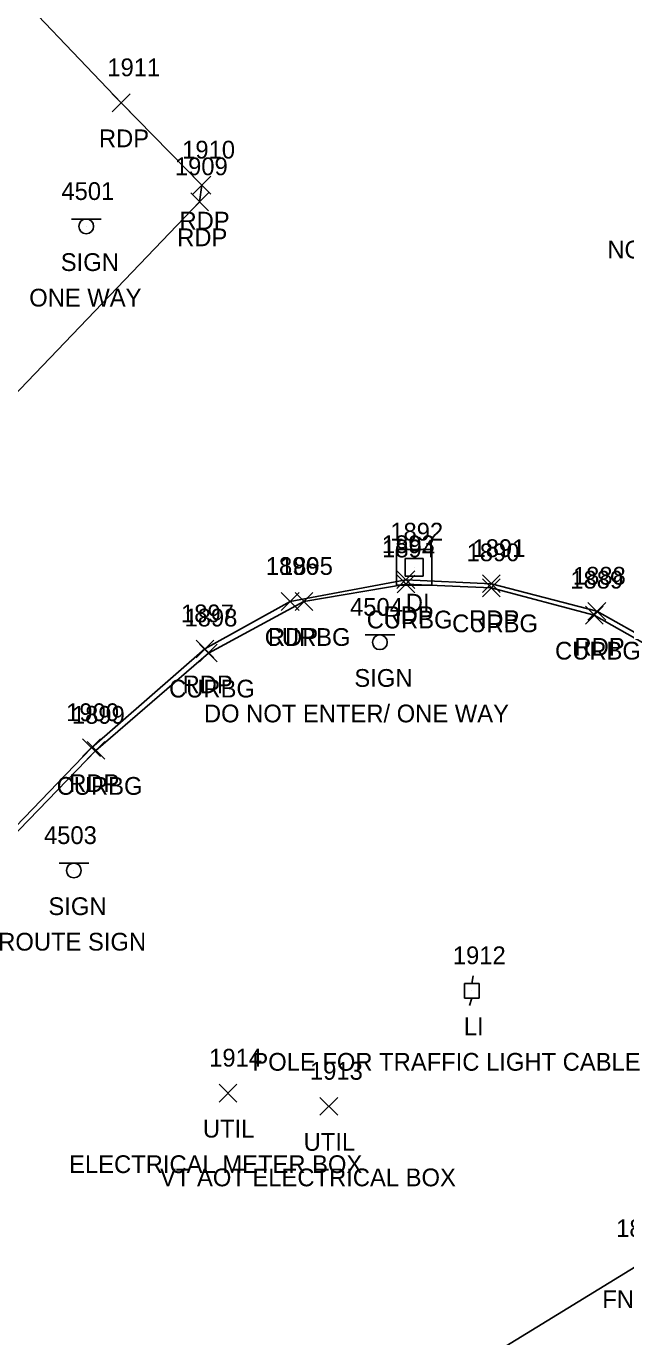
# Model space of a CAD drawing. Extents: x 1690689 to 1696275, y 438760 to 444007.
# Drawn here: x 1691729.4 to 1691796.9, y 439182.5 to 439330.1 of the extents above; entities that cross this region are included whole.
import ezdxf

# ---------------------------------------------------------------- set-up
doc = ezdxf.new("R2010")
doc.units = 0
for name, color, linetype in [('D_A', 7, 'Continuous'), ('D_I', 7, 'Continuous'), ('DS', 7, 'Continuous'), ('L_A', 7, 'Continuous'), ('L_I', 7, 'Continuous'), ('LFNC', 7, 'Continuous'), ('P_A', 7, 'Continuous'), ('P_I', 7, 'Continuous'), ('P_TIC', 7, 'Continuous'), ('PET', 7, 'Continuous'), ('R_A', 7, 'Continuous'), ('R_I', 7, 'Continuous'), ('R_TIC', 7, 'Continuous'), ('RC', 7, 'Continuous'), ('S_A', 7, 'Continuous'), ('S_C', 7, 'Continuous'), ('S_I', 7, 'Continuous'), ('SSGN', 7, 'Continuous'), ('U_A', 7, 'Continuous'), ('U_C', 7, 'Continuous'), ('U_I', 7, 'Continuous'), ('UDEFAULT', 7, 'Continuous'), ('ULP', 7, 'Continuous')]:
    doc.layers.add(name, color=color, linetype=linetype)

msp = doc.modelspace()

# ---------------------------------------------------------------- linework, layer by layer
at = {"layer": 'DS'}
for p, q in [((1691771.1, 439271.16), (1691775.1, 439271.16)), ((1691771.1, 439267.16), (1691771.1, 439271.16)), ((1691772.1, 439268.16), (1691772.1, 439270.16)), ((1691772.1, 439270.16), (1691774.1, 439270.16)), ((1691774.1, 439270.16), (1691774.1, 439268.16)), ((1691775.1, 439271.16), (1691775.1, 439267.16)), ((1691773.11, 439269.17), (1691773.11, 439269.17)), ((1691773.11, 439269.17), (1691773.11, 439269.17)), ((1691775.1, 439267.16), (1691771.1, 439267.16)), ((1691774.1, 439268.16), (1691772.1, 439268.16))]:
    msp.add_line(p, q, dxfattribs=at)
at = {"layer": 'LFNC'}
msp.add_lwpolyline([(1691757.36, 439165.44), (1691798.52, 439190.71), (1691844.54, 439219.14)], dxfattribs=at)
at = {"layer": 'P_TIC'}
for points in [[(1691739.13, 439320.47), (1691741.13, 439322.47)], [(1691741.13, 439320.47), (1691739.13, 439322.47)], [(1691748.2, 439311.2), (1691750.2, 439313.2)], [(1691750.2, 439311.2), (1691748.2, 439313.2)], [(1691747.95, 439309.32), (1691749.95, 439311.32)], [(1691749.95, 439309.32), (1691747.95, 439311.32)], [(1691771.16, 439266.75), (1691773.16, 439268.75)], [(1691773.16, 439266.75), (1691771.16, 439268.75)], [(1691780.79, 439266.31), (1691782.79, 439268.31)], [(1691782.79, 439266.31), (1691780.79, 439268.31)], [(1691758.15, 439264.3), (1691760.15, 439266.3)], [(1691760.15, 439264.3), (1691758.15, 439266.3)], [(1691792.66, 439263.2), (1691794.66, 439265.2)], [(1691794.66, 439263.2), (1691792.66, 439265.2)], [(1691748.55, 439258.96), (1691750.55, 439260.96)], [(1691750.55, 439258.96), (1691748.55, 439260.96)], [(1691735.79, 439247.83), (1691737.79, 439249.83)], [(1691737.79, 439247.83), (1691735.79, 439249.83)]]:
    msp.add_lwpolyline(points, dxfattribs=at)
at = {"layer": 'PET'}
for points in [[(1691635.64, 439190.05), (1691676.02, 439233.65), (1691723.65, 439283.92), (1691748.95, 439310.32), (1691749.2, 439312.2), (1691740.13, 439321.47), (1691725.27, 439337.07), (1691702.51, 439363.5), (1691678.2, 439394.68), (1691673.58, 439401.13), (1691654.57, 439427.19), (1691640.83, 439446.56), (1691618.23, 439480.22), (1691600.47, 439509.04), (1691582.54, 439539.92), (1691568.85, 439565.16), (1691555.7, 439590.13)], [(1691879.71, 439146.4), (1691887.29, 439151.26), (1691891.2, 439160.18), (1691892.92, 439173.27), (1691891.62, 439183.5), (1691889.41, 439189.26), (1691882.28, 439196.79), (1691847.76, 439223.08), (1691819.3, 439246.34), (1691802.22, 439259.4), (1691793.66, 439264.2), (1691781.79, 439267.31), (1691772.16, 439267.75), (1691759.15, 439265.3), (1691749.55, 439259.96), (1691736.79, 439248.83), (1691704.51, 439215.28), (1691660.95, 439169.53)]]:
    msp.add_lwpolyline(points, dxfattribs=at)
at = {"layer": 'R_TIC'}
for points in [[(1691771.18, 439266.27), (1691773.18, 439268.27)], [(1691773.18, 439266.27), (1691771.18, 439268.27)], [(1691780.78, 439265.84), (1691782.78, 439267.84)], [(1691782.78, 439265.84), (1691780.78, 439267.84)], [(1691759.7, 439264.3), (1691761.7, 439266.3)], [(1691761.7, 439264.3), (1691759.7, 439266.3)], [(1691792.37, 439262.76), (1691794.37, 439264.76)], [(1691794.37, 439262.76), (1691792.37, 439264.76)], [(1691748.94, 439258.49), (1691750.94, 439260.49)], [(1691750.94, 439258.49), (1691748.94, 439260.49)], [(1691736.29, 439247.53), (1691738.29, 439249.53)], [(1691738.29, 439247.53), (1691736.29, 439249.53)]]:
    msp.add_lwpolyline(points, dxfattribs=at)
at = {"layer": 'RC'}
msp.add_lwpolyline([(1691891.4, 439183.61), (1691888.94, 439188.91), (1691881.87, 439196.3), (1691847.41, 439222.5), (1691819.04, 439246.01), (1691801.91, 439258.9), (1691793.37, 439263.76), (1691781.78, 439266.84), (1691772.18, 439267.27), (1691760.7, 439265.3), (1691749.94, 439259.49), (1691737.29, 439248.53), (1691704.84, 439214.94), (1691660.93, 439168.79)], dxfattribs=at)
at = {"layer": 'SSGN'}
for p, q in [((1691734.55, 439308.38), (1691737.88, 439308.38)), ((1691736.19, 439307.55), (1691736.19, 439307.55)), ((1691767.59, 439261.54), (1691770.92, 439261.54)), ((1691769.24, 439260.71), (1691769.24, 439260.71)), ((1691733.16, 439235.83), (1691736.49, 439235.83)), ((1691734.8, 439235), (1691734.8, 439235))]:
    msp.add_line(p, q, dxfattribs=at)
for centre in [(1691736.19, 439307.55), (1691769.24, 439260.71), (1691734.8, 439235)]:
    msp.add_circle(centre, 0.833, dxfattribs=at)
at = {"layer": 'UDEFAULT'}
for points in [[(1691751.16, 439208.92), (1691753.16, 439210.92)], [(1691753.16, 439208.92), (1691751.16, 439210.92)], [(1691762.49, 439207.43), (1691764.49, 439209.43)], [(1691764.49, 439207.43), (1691762.49, 439209.43)]]:
    msp.add_lwpolyline(points, dxfattribs=at)
at = {"layer": 'ULP'}
for p, q in [((1691779.75, 439223.12), (1691779.58, 439222.29)), ((1691778.75, 439220.62), (1691778.75, 439222.29)), ((1691778.75, 439222.29), (1691780.41, 439222.29)), ((1691779.58, 439221.45), (1691779.58, 439221.45)), ((1691780.41, 439222.29), (1691780.41, 439220.62)), ((1691780.41, 439220.62), (1691778.75, 439220.62)), ((1691779.33, 439219.79), (1691779.58, 439220.62))]:
    msp.add_line(p, q, dxfattribs=at)

# ---------------------------------------------------------------- texts
at = {"layer": 'D_A'}
msp.add_text('DI', height=2, dxfattribs=at).set_placement((1691772.16, 439264.17))
at = {"layer": 'D_I'}
msp.add_text('1892', height=2, dxfattribs=at).set_placement((1691770.41, 439272.17))
at = {"layer": 'L_A'}
msp.add_text('FNCHL', height=2, dxfattribs=at).set_placement((1691794.27, 439185.71))
at = {"layer": 'L_I'}
msp.add_text('1882', height=2, dxfattribs=at).set_placement((1691795.83, 439193.71))
at = {"layer": 'P_A'}
for p in [(1691737.62, 439316.47), (1691746.69, 439307.2), (1691746.43, 439305.32), (1691769.65, 439262.75), (1691779.28, 439262.31), (1691756.64, 439260.3), (1691791.14, 439259.2), (1691747.04, 439254.96), (1691734.28, 439243.83)]:
    msp.add_text('RDP', height=2, dxfattribs=at).set_placement(p)
at = {"layer": 'P_I'}
for s, p in [('1911', (1691738.57, 439324.47)), ('1910', (1691746.99, 439315.2)), ('1909', (1691746.17, 439313.32)), ('1893', (1691769.46, 439270.75)), ('1891', (1691779.66, 439270.31)), ('1896', (1691756.4, 439268.3)), ('1888', (1691790.96, 439267.2)), ('1897', (1691746.86, 439262.96)), ('1900', (1691733.93, 439251.83))]:
    msp.add_text(s, height=2, dxfattribs=at).set_placement(p)
at = {"layer": 'R_A'}
for p in [(1691767.76, 439262.27), (1691777.37, 439261.84), (1691756.28, 439260.3), (1691788.95, 439258.76), (1691745.52, 439254.49), (1691732.87, 439243.53)]:
    msp.add_text('CURBG', height=2, dxfattribs=at).set_placement(p)
at = {"layer": 'R_I'}
for s, p in [('1894', (1691769.49, 439270.27)), ('1890', (1691779, 439269.84)), ('1895', (1691758, 439268.3)), ('1889', (1691790.67, 439266.76)), ('1898', (1691747.25, 439262.49)), ('1899', (1691734.58, 439251.53))]:
    msp.add_text(s, height=2, dxfattribs=at).set_placement(p)
at = {"layer": 'S_A'}
for p in [(1691733.33, 439302.53), (1691766.37, 439255.69), (1691731.94, 439229.98)]:
    msp.add_text('SIGN', height=2, dxfattribs=at).set_placement(p)
at = {"layer": 'S_C'}
for s, p in [('NO LEFT TURN', (1691794.84, 439303.95)), ('ONE WAY', (1691729.78, 439298.53)), ('DO NOT ENTER/ ONE WAY', (1691749.44, 439251.69)), ('ROUTE SIGN', (1691726.29, 439225.98))]:
    msp.add_text(s, height=2, dxfattribs=at).set_placement(p)
at = {"layer": 'S_I'}
for s, p in [('4501', (1691733.4, 439310.53)), ('4504', (1691765.88, 439263.69)), ('4503', (1691731.44, 439237.98))]:
    msp.add_text(s, height=2, dxfattribs=at).set_placement(p)
at = {"layer": 'U_A'}
for s, p in [('LI', (1691778.68, 439216.45)), ('UTIL', (1691749.32, 439204.92)), ('UTIL', (1691760.66, 439203.43))]:
    msp.add_text(s, height=2, dxfattribs=at).set_placement(p)
at = {"layer": 'U_C'}
for s, p in [('POLE FOR TRAFFIC LIGHT CABLE', (1691754.89, 439212.45)), ('ELECTRICAL METER BOX', (1691734.27, 439200.92)), ('VT AOT ELECTRICAL BOX', (1691744.5, 439199.43))]:
    msp.add_text(s, height=2, dxfattribs=at).set_placement(p)
at = {"layer": 'U_I'}
for s, p in [('1912', (1691777.45, 439224.45)), ('1914', (1691750.03, 439212.92)), ('1913', (1691761.37, 439211.43))]:
    msp.add_text(s, height=2, dxfattribs=at).set_placement(p)

doc.saveas('drawing.dxf')
